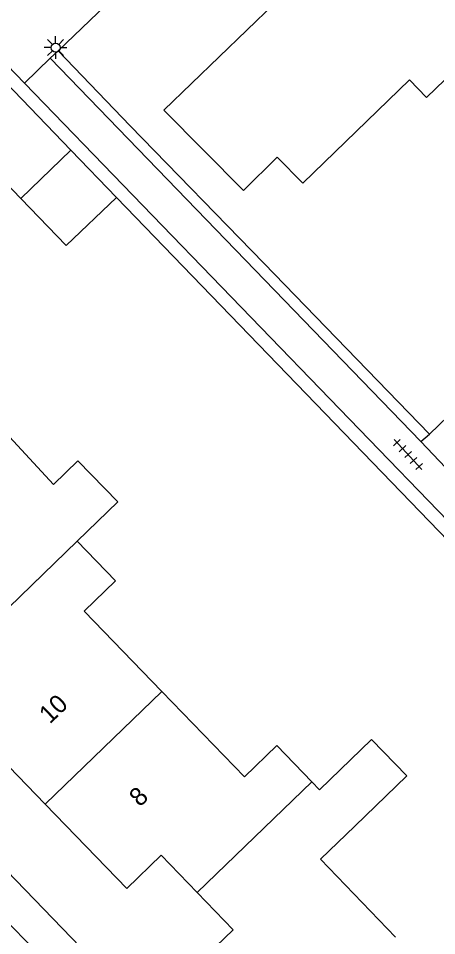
# Model space of a CAD drawing. Extents: x 137999 to 141000, y 397500 to 400501.
# Drawn here: x 138571.7 to 138594.7, y 399296.5 to 399346.9 of the extents above; entities that cross this region are included whole.
import ezdxf

# ---------------------------------------------------------------- set-up
doc = ezdxf.new("R2010")
doc.units = 0
for name, color, linetype in [('gg-afsc-erfafscheiding', 7, 'Continuous'), ('gg-afsc-muur', 7, 'Continuous'), ('gg-anno-huisnummerreeks BGT', 7, 'Continuous'), ('gg-bbg-bijgebouw', 7, 'Continuous'), ('gg-bbg-gedigitaliseerde bebouwing', 7, 'Continuous'), ('gg-bbg-hoofdgebouw', 7, 'Continuous'), ('gg-bbg-tussenscheiding', 7, 'Continuous'), ('gg-knt-verharding', 7, 'Continuous'), ('gt-grn-weggrens', 7, 'Continuous'), ('gt-symb-lichtmast', 7, 'Continuous'), ('gt-symb-tegel verharding', 7, 'Continuous')]:
    doc.layers.add(name, color=color, linetype=linetype)

# ---------------------------------------------------------------- blocks, each defined once
blk = doc.blocks.new('gt0-TEG1')
at = {"layer": 'gt-symb-tegel verharding'}
for p, q in [((-1.125, 0), (1.125, 0)), ((-0.9, -0.25), (-0.9, 0.25)), ((-0.45, -0.25), (-0.45, 0.25)), ((0, -0.25), (0, 0.25)), ((0.45, -0.25), (0.45, 0.25)), ((0.9, -0.25), (0.9, 0.25))]:
    blk.add_line(p, q, dxfattribs=at)
blk = doc.blocks.new('gt0-LMAST')
at = {"layer": 'gt-symb-lichtmast'}
for p, q in [((-0.005, 0.246), (-0.005, 0.621)), ((-0.182, 0.173), (-0.447, 0.438)), ((0.172, 0.173), (0.437, 0.438)), ((-0.255, -0.004), (-0.63, -0.004)), ((-0.182, -0.181), (-0.447, -0.446)), ((-0.005, -0.254), (-0.005, -0.629)), ((0.437, -0.446), (0.172, -0.181)), ((0.245, -0.004), (0.62, -0.004))]:
    blk.add_line(p, q, dxfattribs=at)
blk.add_circle((-0.005, -0.004), 0.25, dxfattribs=at)

msp = doc.modelspace()

# ---------------------------------------------------------------- linework, layer by layer
at = {"layer": 'gg-afsc-erfafscheiding'}
for p, q in [((138594.27, 399324.093), (138626.367, 399355.056)), ((138573.864, 399345.159), (138577.819, 399341.032)), ((138577.07, 399337.1), (138606.61, 399306.49)), ((138585.167, 399333.482), (138594.27, 399324.093))]:
    msp.add_line(p, q, dxfattribs=at)
at = {"layer": 'gg-afsc-muur'}
msp.add_line((138577.819, 399341.032), (138585.167, 399333.482), dxfattribs=at)
at = {"layer": 'gg-bbg-bijgebouw'}
for p, q in [((138570.06, 399344.37), (138574.566, 399339.697)), ((138571.82, 399337.042), (138567.31, 399341.72)), ((138574.566, 399339.697), (138577.07, 399337.1))]:
    msp.add_line(p, q, dxfattribs=at)
msp.add_lwpolyline([(138577.07, 399337.1), (138574.32, 399334.45), (138571.82, 399337.042)], dxfattribs=at)
at = {"layer": 'gg-bbg-gedigitaliseerde bebouwing'}
for p, q in [((138573.606, 399321.327), (138569.354, 399325.936)), ((138587.812, 399304.981), (138588.236, 399304.542))]:
    msp.add_line(p, q, dxfattribs=at)
for points in [[(138573.606, 399321.327), (138574.954, 399322.629), (138577.146, 399320.362), (138574.911, 399318.201)], [(138574.911, 399318.201), (138577.012, 399316.028), (138575.292, 399314.366), (138579.575, 399309.934)], [(138579.575, 399309.934), (138584.104, 399305.249), (138585.887, 399306.973), (138587.812, 399304.981)], [(138588.236, 399304.542), (138591.084, 399307.3), (138593.02, 399305.301), (138590.17, 399302.541)], [(138592.395, 399296.443), (138588.285, 399300.719), (138590.17, 399302.541)]]:
    msp.add_lwpolyline(points, dxfattribs=at)
at = {"layer": 'gg-bbg-hoofdgebouw'}
msp.add_line((138585.763, 399347.766), (138579.681, 399341.886), dxfattribs=at)
for points in [[(138597.104, 399345.478), (138594.11, 399342.59), (138593.18, 399343.56), (138587.31, 399337.89)], [(138579.681, 399341.886), (138584.056, 399337.478), (138585.901, 399339.31), (138587.31, 399337.89)], [(138573.163, 399303.741), (138568.66, 399308.4), (138570.56, 399310.23), (138568.693, 399312.164)], [(138581.505, 399298.89), (138579.53, 399300.94), (138577.64, 399299.11), (138573.163, 399303.741)], [(138581.505, 399298.89), (138583.48, 399296.84), (138581.59, 399295.02), (138586.097, 399290.352)]]:
    msp.add_lwpolyline(points, dxfattribs=at)
at = {"layer": 'gg-bbg-tussenscheiding'}
for p, q in [((138574.566, 399339.697), (138571.82, 399337.042)), ((138574.911, 399318.201), (138568.693, 399312.164)), ((138573.163, 399303.741), (138579.575, 399309.934)), ((138581.505, 399298.89), (138587.812, 399304.981))]:
    msp.add_line(p, q, dxfattribs=at)
at = {"layer": 'gg-knt-verharding'}
for p, q in [((138573.864, 399345.159), (138621.021, 399390.671)), ((138572.015, 399343.376), (138570.575, 399344.865)), ((138573.44, 399344.75), (138593.797, 399323.679)), ((138614.16, 399299.79), (138572.015, 399343.376)), ((138592.65, 399277.79), (138547.64, 399324.23)), ((138593.797, 399323.679), (138594.27, 399324.093)), ((138564.572, 399303.991), (138573.307, 399294.98))]:
    msp.add_line(p, q, dxfattribs=at)
at = {"layer": 'gt-grn-weggrens'}
for p, q in [((138573.864, 399345.159), (138573.44, 399344.75)), ((138573.44, 399344.75), (138572.015, 399343.376)), ((138593.797, 399323.679), (138595.148, 399322.246))]:
    msp.add_line(p, q, dxfattribs=at)

# ---------------------------------------------------------------- block references
at = {"layer": 'gt-symb-lichtmast'}
msp.add_blockref('gt0-LMAST', (138573.735, 399345.339), dxfattribs=at)
at = {"layer": 'gt-symb-tegel verharding', "rotation": 133.01389341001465}
msp.add_blockref('gt0-TEG1', (138593.09, 399322.965), dxfattribs=at)

# ---------------------------------------------------------------- texts
at = {"layer": 'gg-anno-huisnummerreeks BGT'}
for s, p in [('10', (138573.412, 399308.12)), ('8', (138578.362, 399303.56))]:
    msp.add_text(s, height=1, rotation=44, dxfattribs=at).set_placement(p)

doc.saveas('drawing.dxf')
